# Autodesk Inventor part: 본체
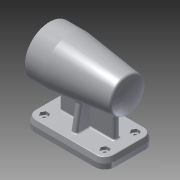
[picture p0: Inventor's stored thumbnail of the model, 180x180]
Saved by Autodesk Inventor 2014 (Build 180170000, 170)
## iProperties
Created: 2017-01
Part Number: 본체
Material: 알루미늄 6061
Document SubType Name: Modeling
Designer: owner
Density: 2.71 g/cm^3
Appearance: 알루미늄 - 평지
Mass: 794.538 g
Surface Area: 662.982 cm^2
Volume: 293.187 cm^3
Author: owner
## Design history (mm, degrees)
sketch "스케치1"
  geometry: L1 (-56, 35)-(56, 35); L2 (56, 35)-(56, -35); L3 (56, -35)-(-56, -35); L4 (-56, -35)-(-56, 35); 1 further point
  constraints: 8 end point, 2 parallel, 1 horizontal, 1 perpendicular
  dimensions: "d0" = 70 distance between parallel lines of L3 L1; "d1" = 112 distance between parallel lines of L4 L2; "d2" = 35 distance from line of point (0, 0) L1; "d3" = 56 distance from line of L2 point (0, 0)
extrude "돌출1" new body sketch "스케치1" distance "d4" = 7; taper "d5" = 0 deg
fillet "모깎기1" dims "d6" = 14
sketch "스케치2"
  geometry: L1 (-56, 0)-(-56, 7) reference; L2 (-56, 7)-(-42, 7) reference; L3 (56, 7)-(56, 0) reference; L4 (42, 7)-(56, 7) reference; L5 (-56, 7)-(-54.124, 14); L6 (-54.124, 14)-(54.124, 14); L7 (54.124, 14)-(56, 7); 1 further point
  constraints: 6 end point, 1 parallel
  dimensions: "d7" = 7 distance between parallel lines of L2 L6; "d8" = 15 deg angle of L1 L5; "d9" = 15 deg angle of L7 L3
sketch "스케치3"
  geometry: L1 (-56, 21)-(-56, -21) reference; L2 (-42, -35)-(42, -35) reference; L3 (56, -21)-(56, 21) reference; L4 (42, 35)-(-42, 35) reference; L5 (-54.124, -21)-(-54.124, 21); L6 (-42, 33.124)-(42, 33.124); L7 (54.124, 21)-(54.124, -21); L8 (42, -33.124)-(-42, -33.124); L9 (-54.124, 0)-(-56, 0) reference; L10 (-54.124, 0)-(-54.124, 5); A1 r 14 centre (-42, 21) between (-42, 35) and (-56, 21) reference; A2 r 14 centre (-42, -21) between (-56, -21) and (-42, -35) reference; A3 r 14 centre (42, -21) between (42, -35) and (56, -21) reference; A4 r 14 centre (42, 21) between (56, 21) and (42, 35) reference; A5 r 12.124 centre (-42, 21) between (-42, 33.124) and (-54.124, 21); A6 r 12.124 centre (42, 21) between (54.124, 21) and (42, 33.124); A7 r 12.124 centre (42, -21) between (42, -33.124) and (54.124, -21); A8 r 12.124 centre (-42, -21) between (-54.124, -21) and (-42, -33.124); 2 further points
  constraints: 10 end point, 8 point on circle, 4 centre point, 1 collinear, 1 perpendicular, 7 other
  dimensions: "d11" = 5 distance of L9.start L10.end
node "작업 평면1"
sketch "스케치4"
  geometry: L1 (12.124, 33.124)-(96.124, 33.124) reference; L2 (0, -21)-(0, 21) reference; L3 (96.124, -33.124)-(12.124, -33.124) reference; L4 (108.249, 21)-(108.249, -21) reference; L5 (96.124, 33.124)-(12.124, 33.124); L6 (0, 21)-(0, -21); L7 (12.124, -33.124)-(96.124, -33.124); L8 (108.249, -21)-(108.249, 21); A1 r 12.124 centre (12.124, 21) between (12.124, 33.124) and (0, 21) reference; A2 r 12.124 centre (12.124, -21) between (0, -21) and (12.124, -33.124) reference; A3 r 12.124 centre (96.124, -21) between (96.124, -33.124) and (108.249, -21) reference; A4 r 12.124 centre (96.124, 21) between (108.249, 21) and (96.124, 33.124) reference; A5 r 12.124 centre (12.124, 21) between (12.124, 33.124) and (0, 21); A6 r 12.124 centre (12.124, -21) between (0, -21) and (12.124, -33.124); A7 r 12.124 centre (96.124, -21) between (96.124, -33.124) and (108.249, -21); A8 r 12.124 centre (96.124, 21) between (108.249, 21) and (96.124, 33.124); 1 further point
  constraints: 8 end point, 8 point on circle, 4 centre point, 1 collinear, 7 other
sketch "스케치5"
  geometry: L1 (-56, 21)-(-56, -21) reference; L2 (-42, -35)-(42, -35) reference; L3 (56, -21)-(56, 21) reference; L4 (42, 35)-(-42, 35) reference; L5 (-56, 21)-(-56, -21); L6 (-42, -35)-(42, -35); L7 (56, -21)-(56, 21); L8 (42, 35)-(-42, 35); A1 r 14 centre (-42, 21) between (-42, 35) and (-56, 21) reference; A2 r 14 centre (-42, -21) between (-56, -21) and (-42, -35) reference; A3 r 14 centre (42, -21) between (42, -35) and (56, -21) reference; A4 r 14 centre (42, 21) between (56, 21) and (42, 35) reference; A5 r 14 centre (-42, 21) between (-42, 35) and (-56, 21); A6 r 14 centre (-42, -21) between (-56, -21) and (-42, -35); A7 r 14 centre (42, -21) between (42, -35) and (56, -21); A8 r 14 centre (42, 21) between (56, 21) and (42, 35); 1 further point
  constraints: 8 end point, 8 point on circle, 4 centre point, 1 collinear, 7 other
feature "로프트1" dims "d12" = 0, "d13" = 90 deg, "d14" = 0, "d15" = 90 deg
sketch "스케치6"
  geometry: L1 (42, 14)-(-42, 14) reference; L2 (-54.124, 14)-(-42, 14) reference; L3 (-56, 7)-(-54.124, 14) reference; L4 (-56, 0)-(-56, 7) reference; L5 (54.124, 14)-(56, 7) reference; L6 (42, 14)-(54.124, 14) reference; L7 (56, 7)-(56, 0) reference; L8 (-50, 74)-(59.367, 74); L9 (-42, 0)-(-56, 0) reference; L10 (56, 40)-(56, 53); L11 (56, 53)-(41, 53); L12 (41, 53)-(41, 53); L13 (38, 50)-(-10, 50); L14 (-13, 53)-(-13, 53); L15 (-13, 53)-(-24.7, 53); L16 (-25, 53.3)-(-25, 56.5); L17 (-25, 56.5)-(-42.7, 56.5); L18 (-43, 56.8)-(-43, 58); L19 (-43, 58)-(-46.7, 58); L20 (-47, 58.3)-(-47, 63.5); L21 (-47, 63.5)-(-47, 63.5); L22 (-50, 66.5)-(-50, 74); L23 (56, 40)-(28, 40); L24 (28, 40)-(-52.27, 49.856); L25 (-50, 74)-(-56, 74); L26 (56, 0)-(56, 7) reference; A1 r 80 centre (24, 74) between (-52.27, 49.856) and (-56, 74); A2 r 3 centre (38, 53) between (38, 50) and (41, 53); A3 r 3 centre (-10, 53) between (-13, 53) and (-10, 50); A4 r 0.3 centre (-24.7, 53.3) between (-25, 53.3) and (-24.7, 53); A5 r 0.3 centre (-42.7, 56.8) between (-43, 56.8) and (-42.7, 56.5); A6 r 0.3 centre (-46.7, 58.3) between (-47, 58.3) and (-46.7, 58); A7 r 3 centre (-47, 66.5) between (-50, 66.5) and (-47, 63.5); 5 further points
  constraints: 34 end point, 14 point on circle, 12 parallel, 12 tangent, 9 point on line, 7 centre point, 4 perpendicular, 3 equal radius, 2 collinear
  dimensions: "d16" = 74 distance between parallel lines of L9 L8; "d17" = 160 diameter of A1; "d18" = 15 distance between parallel lines of L12 L10; "d19" = 54 distance between parallel lines of L14 L12; "d20" = 12 distance between parallel lines of L16 L14; "d21" = 18 distance between parallel lines of L18 L16; "d22" = 4 distance between parallel lines of L20 L18; "d23" = 3 distance between parallel lines of L22 L20; "d24" = 7 deg angle of L8 L24; "d25" = 68 diameter of L23 L8; "d26" = 42 diameter of L11 L8; "d27" = 48 diameter of L13 L8; "d28" = 42 diameter of L15 L8; "d29" = 35 diameter of L17 L8; "d30" = 32 diameter of L19 L8; "d31" = 21 diameter of L21 L8; "d32" = 112 distance from line of L25.end L10; "d33" = 28 distance of L10.start L23.end; "d34" = 3 radius of A2; "d76" = 0.3 radius of A4; "d77" = 3 radius of A7
revolve "회전1" sketch "스케치6" stored, may be unused: angle "d35" = 90 deg
fillet "모깎기2" dims "d36" = 3
sketch "스케치7"
  geometry: L1 (28, 40)-(-50.331, 49.618) reference; L2 (42, 14)-(-42, 14) reference; L3 (-10, 50)-(38, 50) reference; L4 (38, 50)-(-38, 50); L5 (-38, 50)-(-38, 14); L6 (-38, 14)-(38, 14); L7 (38, 14)-(38, 50); L8 (-56, 0)-(-56, 7) reference; L9 (56, 7)-(56, 0) reference; 1 further point
  constraints: 8 end point, 2 parallel, 2 point on line, 1 horizontal, 1 perpendicular
  dimensions: "d37" = 18 distance from line of L8.start L5; "d38" = 18 distance between parallel lines of L9 L7
extrude "돌출2" join sketch "스케치7" stored distance "d39" = 8; taper "d40" = 0 deg
sketch "스케치8"
  geometry: L1 (21, 14)-(-21, 14) reference; L2 (-33.124, 14)-(-21, 14) reference; L3 (21, 14)-(33.124, 14) reference; L4 (-15.632, 55.789)-(-23, 14); L5 (-35, 0)-(-35, 7) reference; 2 further points
  constraints: 2 end point, 1 point on line, 2 other
  dimensions: "d41" = 12 distance from line of L5 L4.end; "d42" = 100 deg angle of L2 L4
feature "리브1" sketch "스케치8" dims "d43" = 1, "d44" = 8, "d45" = 0, "d46" = 0, "d47" = 1, "d48" = 1
sketch "스케치9"
  geometry: C1 r 21 at (0, 0) reference; 2 further points
  constraints: 1 horizontal alignment
  dimensions: "d49" = 26 distance of point (26, 0) C1.centre
hole "구멍1" sketch "스케치9" at (26, 0) diameter "d50" = 3.242; stored, may be unused: countersink angle "d54" = 90 deg, drill point angle "d56" = 118 deg; dims "d51" = 8, "d52" = 4, "d53" = 2, "d55" = 11
fillet "모깎기3" dims "d60" = 3
fillet "모깎기4" dims "d61" = 1
chamfer "모따기1" distance "d62" = 1; stored, may be unused: second distance "d63" = 2, angle "d64" = 45 deg
sketch "스케치10" dims "d65" = 10
  geometry: L1 (2.887, 6.357)-(-2.887, 6.357); L2 (-2.887, 6.357)-(-5.774, 11.357); L3 (-5.774, 11.357)-(-2.887, 16.357); L4 (-2.887, 16.357)-(2.887, 16.357); L5 (2.887, 16.357)-(5.774, 11.357); L6 (5.774, 11.357)-(2.887, 6.357); L7 (0, 11.357)-(0, 6.357); A1 r 11.357 centre (0, 11.357) between (-11.357, 11.357) and (0, 0) reference; 2 further points
  constraints: 14 end point, 2 coincident, 1 midpoint, 1 perpendicular, 1 vertical, 1 vertical alignment, 15 other
extrude "돌출3" cut sketch "스케치10" distance "d66" = 4; taper "d67" = 0 deg
sketch "스케치11"
  geometry: C1 r 2.5 at (0, 11.357); A1 r 11.357 centre (0, 11.357) between (-11.357, 11.357) and (0, 0) reference; 1 further point
  constraints: 1 centre point, 1 coincident
  dimensions: "d68" = 5 diameter of C1
extrude "돌출4" cut sketch "스케치11" distance "d69" = 100; taper "d70" = 0 deg
fillet "모깎기5" dims "d71" = 3
fillet "모깎기6" dims "d72" = 2
sketch "스케치13"
  geometry: L1 (0, 0)-(84, 0) reference; 3 further points
  constraints: 1 midpoint, 1 vertical alignment, 1 other
  dimensions: "d73" = 4 distance of point (42, 0) point (42, -4)
extrude "돌출5" join sketch "스케치13" distance "d74" = 0.5; taper "d75" = 0 deg
node "솔리드1"
mirror "대칭1"
pattern_circular "원형 패턴1" dims angle "d58" = 360 deg
mirror "대칭2"
mirror "대칭3"
